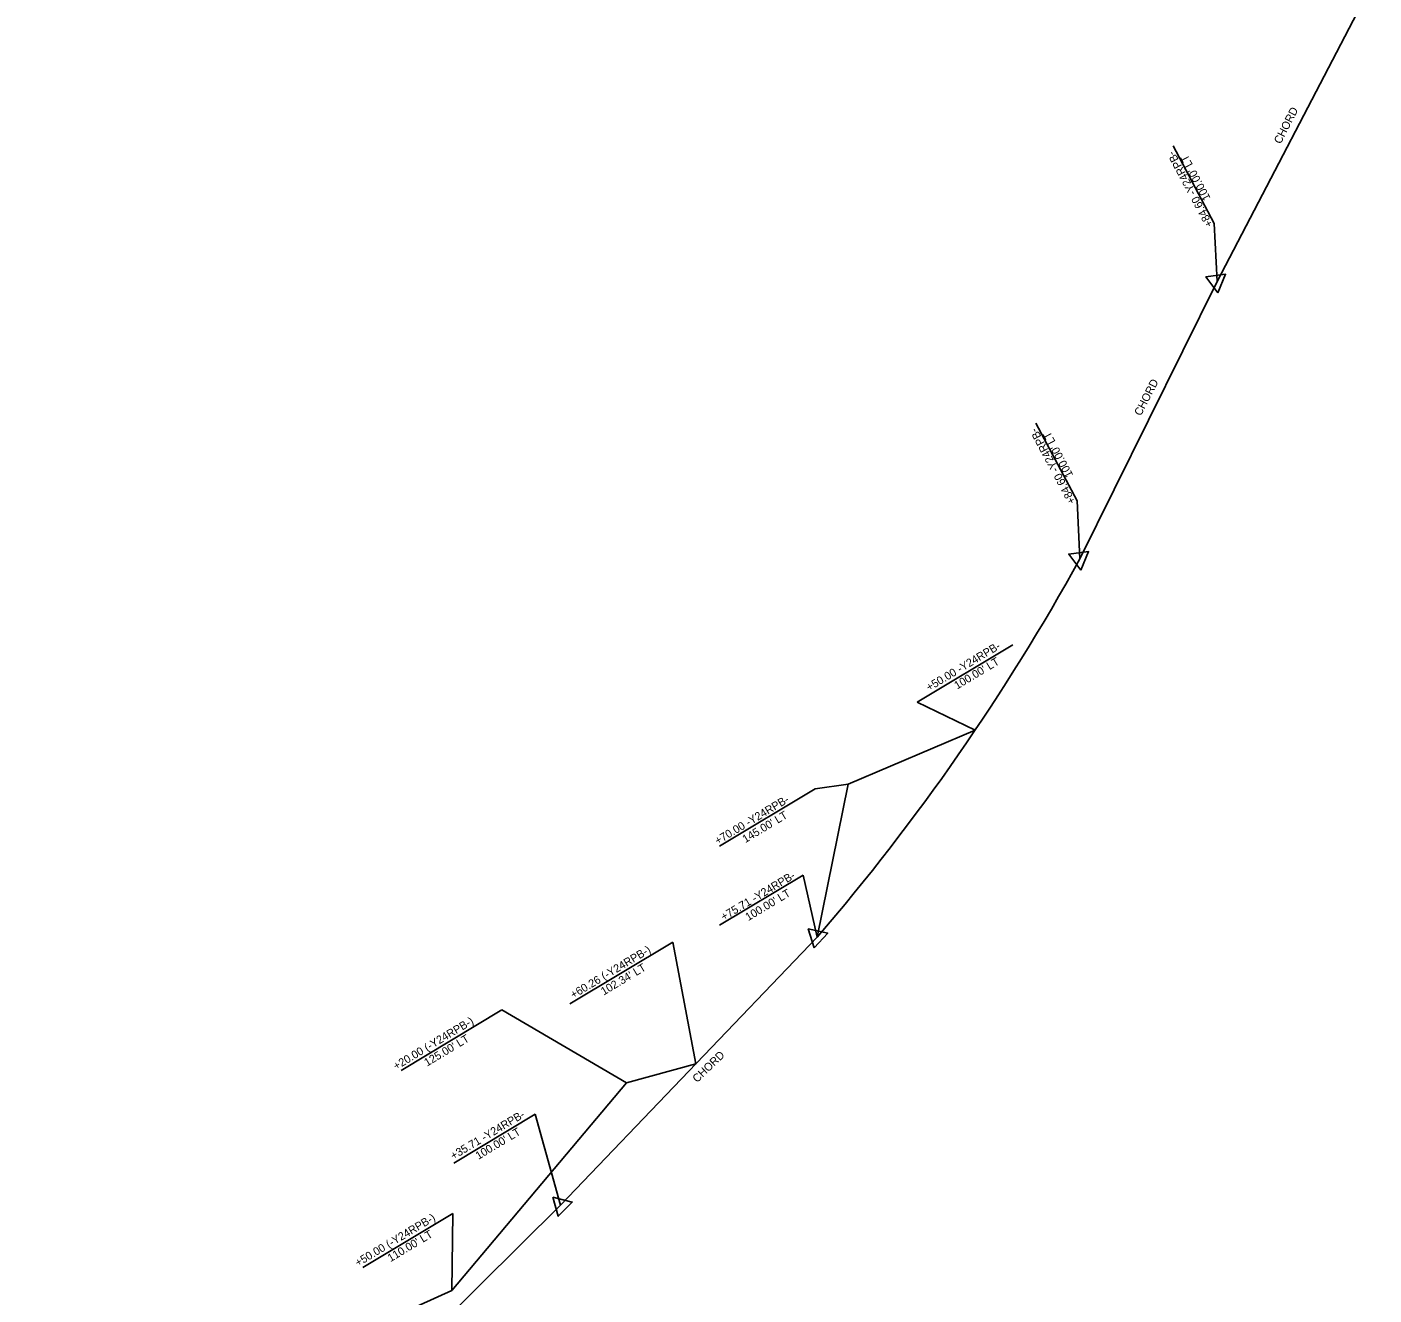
# Model space of a CAD drawing. Extents: x 2390156 to 2403870, y 552315 to 572604.
# Drawn here: x 2400808 to 2401650, y 570376 to 571168 of the extents above; entities that cross this region are included whole.
import ezdxf

# ---------------------------------------------------------------- set-up
doc = ezdxf.new("R2010")
doc.units = 0
for name, color, linetype in [('Prop Dimension', 7, 'Continuous'), ('Prop Dimension Text', 7, 'Continuous'), ('Prop DSN Text', 7, 'Continuous'), ('Prop Roadway Profile Bench Mark Info Text', 7, 'Continuous'), ('Sheet Clip Boundary CELL', 7, 'Continuous'), ('Sheet Plot Border Outside CELL', 7, 'Continuous')]:
    doc.layers.add(name, color=color, linetype=linetype)

msp = doc.modelspace()

# ---------------------------------------------------------------- linework, layer by layer
at = {"layer": 'Prop Dimension'}
for p, q in [((2401424.05, 570782.29), (2401364.38, 570746.44)), ((2401364.38, 570746.44), (2401400.54, 570728.81)), ((2401300.62, 570692.31), (2401240.95, 570656.46)), ((2401300.62, 570692.31), (2401321.23, 570695.2)), ((2401211.62, 570596.46), (2401147.4, 570557.89)), ((2401211.62, 570596.46), (2401226.14, 570520.44)), ((2401104.87, 570554.16), (2401041.94, 570516.36)), ((2401182.7, 570508.47), (2401104.87, 570554.16)), ((2401074.32, 570426.95), (2401017.96, 570393.09)), ((2401074.32, 570426.95), (2401073.57, 570378.83))]:
    msp.add_line(p, q, dxfattribs=at)
at = {"layer": 'Prop Dimension Text'}
for p, q in [((2401551.74, 571009.21), (2401649.85, 571197.54)), ((2401466.06, 570835.94), (2401551.74, 571009.21)), ((2401141.49, 570432.06), (2401301.91, 570599.57)), ((2400995.37, 570287.26), (2401141.49, 570432.06))]:
    msp.add_line(p, q, dxfattribs=at)
msp.add_arc((2400240.17, 571512.1), 1400, 319.32181, 331.12029, dxfattribs=at)
at = {"layer": 'Prop DSN Text'}
for p, q in [((2401321.23, 570695.2), (2401400.54, 570728.81)), ((2401301.91, 570599.57), (2401321.23, 570695.2)), ((2401182.7, 570508.47), (2401226.14, 570520.44)), ((2401073.57, 570378.83), (2401182.7, 570508.47)), ((2400808.12, 570259), (2401073.57, 570378.83))]:
    msp.add_line(p, q, dxfattribs=at)
at = {"layer": 'Prop Roadway Profile Bench Mark Info Text'}
for p, q in [((2401550.02, 571045.55), (2401524.24, 571094.02)), ((2401551.74, 571009.21), (2401550.02, 571045.55)), ((2401464.34, 570872.28), (2401438.57, 570920.75)), ((2401466.06, 570835.94), (2401464.34, 570872.28)), ((2401293.15, 570638.36), (2401240.89, 570606.96)), ((2401301.91, 570599.57), (2401293.15, 570638.36)), ((2401125.64, 570489.02), (2401074.78, 570458.46)), ((2401141.49, 570432.06), (2401125.64, 570489.02))]:
    msp.add_line(p, q, dxfattribs=at)
at = {"layer": 'Sheet Clip Boundary CELL'}
for p, q in [((2401551.39, 571009.4), (2401551.39, 571009.4)), ((2401465.71, 570836.13), (2401465.71, 570836.13)), ((2401301.64, 570599.86), (2401301.64, 570599.86)), ((2401141.88, 570432.12), (2401141.88, 570432.12))]:
    msp.add_line(p, q, dxfattribs=at)
for points in [[(2401552.31, 571002.24), (2401544.75, 571012.17), (2401557.12, 571013.78)], [(2401466.63, 570828.97), (2401459.07, 570838.9), (2401471.44, 570840.51)], [(2401300.1, 570592.82), (2401296.31, 570604.71), (2401308.51, 570602.07)], [(2401136.77, 570437.21), (2401148.83, 570434.02), (2401140.05, 570425.15)]]:
    msp.add_lwpolyline(points, close=True, dxfattribs=at)

# ---------------------------------------------------------------- texts
at = {"layer": 'Sheet Plot Border Outside CELL'}
for s, rotation, p in [('CHORD', 62.82837, (2401591.43, 571094.76)), ('+84.60 -Y24RPB-', 118, (2401549.44, 571044.8)), ("100.00' LT", 118, (2401547.82, 571061.35)), ('CHORD', 62.82837, (2401504.13, 570924.87)), ('+84.60 -Y24RPB-', 118, (2401463.61, 570871.76)), ("100.00' LT", 118, (2401461.98, 570888.32)), ('+50.00 -Y24RPB-', 31, (2401371.84, 570753.06)), ("100.00' LT", 31, (2401389.35, 570754.24)), ('+70.00 -Y24RPB-', 31, (2401239.73, 570657.2)), ("145.00' LT", 31, (2401257, 570658.24)), ('+75.71 -Y24RPB-', 31, (2401243.55, 570609.69)), ("100.00' LT", 31, (2401258.84, 570609.54)), ('+60.26 (-Y24RPB-)', 31, (2401149.54, 570560.96)), ("102.34' LT", 31, (2401168.56, 570563.06)), ('+20.00 (-Y24RPB-)', 31, (2401038.88, 570516.4)), ("125.00' LT", 31, (2401058.13, 570518.64)), ('CHORD', 43.99462, (2401226.86, 570508.36)), ('+35.71 -Y24RPB-', 31, (2401074.61, 570460.35)), ("100.00' LT", 31, (2401090.23, 570460.4)), ('+50.00 (-Y24RPB-)', 31, (2401014.96, 570393.54)), ("110.00' LT", 31, (2401035.29, 570396.43))]:
    msp.add_text(s, height=5, rotation=rotation, dxfattribs=at).set_placement(p)

doc.saveas('drawing.dxf')
